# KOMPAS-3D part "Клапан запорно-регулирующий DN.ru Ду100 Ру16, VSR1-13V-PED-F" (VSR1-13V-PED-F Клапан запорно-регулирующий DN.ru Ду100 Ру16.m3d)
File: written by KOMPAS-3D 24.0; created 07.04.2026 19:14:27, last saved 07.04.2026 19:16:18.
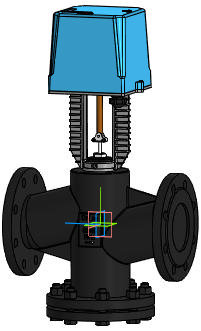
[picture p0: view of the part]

Document properties: Автор: R2D2; Полное имя файла: E:\Работа\Зайцев\Солянка\VSR1-13V-PED-F Клапан запорно-регулирующий DN.ru\DN100\VSR1-13V-PED-F Клапан запорно-регулирующий DN.ru Ду100 Ру16.m3d

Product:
- Part/product: Клапан запорно-регулирующий DN.ru Ду100 Ру16  | designation VSR1-13V-PED-F
    Масса: 33.7
    Раздел спецификации: Прочие изделия
    Примечание: D090-02894

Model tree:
1. Операция без истории:1  (labels: SHAPEOBJECT3D_ATTR_BUTT)

Expressions: VSR1-13V-PED-F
